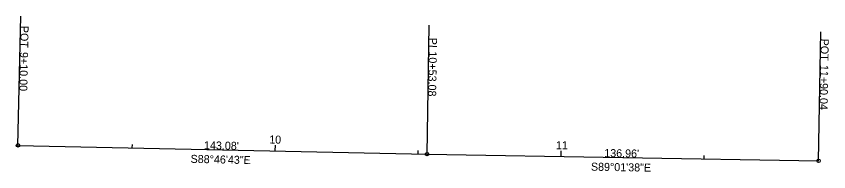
# Model space of a CAD drawing. Extents: x 1652407 to 1652790, y 606471 to 608012.
# Drawn here: x 1652407.2 to 1652691.4, y 606865.9 to 606920.1 of the extents above; entities that cross this region are included whole.
import ezdxf

# ---------------------------------------------------------------- set-up
doc = ezdxf.new("R2010")
doc.units = 0
for name, color, linetype in [('RW_X_CL', 7, 'Continuous'), ('SV_X_Random_Point', 7, 'Continuous'), ('SV_X_Shot_Marker', 7, 'Continuous'), ('UT_X_Water_Cells', 7, 'Continuous'), ('VG_X_Cells', 7, 'Continuous')]:
    doc.layers.add(name, color=color, linetype=linetype)

msp = doc.modelspace()

# ---------------------------------------------------------------- linework, layer by layer
at = {"layer": 'RW_X_CL'}
for p, q in [((1652407.81, 606875.12), (1652550.86, 606872.07)), ((1652550.86, 606872.07), (1652687.8, 606869.74))]:
    msp.add_line(p, q, dxfattribs=at)
at = {"layer": 'SV_X_Random_Point'}
for p, q in [((1652407.81, 606875.12), (1652408.77, 606920.11)), ((1652550.86, 606872.07), (1652551.62, 606917.06)), ((1652687.8, 606869.74), (1652688.56, 606914.74))]:
    msp.add_line(p, q, dxfattribs=at)
for centre in [(1652407.81, 606875.12), (1652550.86, 606872.07), (1652687.8, 606869.74)]:
    msp.add_circle(centre, 0.6, dxfattribs=at)
at = {"layer": 'UT_X_Water_Cells'}
for p, q in [((1652447.8, 606874.27), (1652447.82, 606875.47)), ((1652497.79, 606873.2), (1652497.83, 606875.2)), ((1652547.78, 606872.14), (1652547.8, 606873.34)), ((1652597.77, 606871.27), (1652597.8, 606873.27)), ((1652647.76, 606870.42), (1652647.78, 606871.62))]:
    msp.add_line(p, q, dxfattribs=at)

# ---------------------------------------------------------------- texts
at = {"layer": 'SV_X_Random_Point'}
for s, rotation, p in [('POT', 268.7786, (1652408.74, 606916.81)), ('PI', 269.0273, (1652551.59, 606912.68)), ('POT', 269.0273, (1652688.57, 606912.34)), ('9+10.00', 268.7786, (1652408.55, 606907.69)), ('10+53.08', 269.0273, (1652551.51, 606907.9)), ('11+90.04', 269.0273, (1652688.41, 606903.21))]:
    msp.add_text(s, height=2.8, rotation=rotation, dxfattribs=at).set_placement(p)
at = {"layer": 'SV_X_Shot_Marker'}
for s, rotation, p in [('S88°46\'43"E', 358.7786, (1652468.16, 606869.03)), ('S89°01\'38"E', 359.0273, (1652608.17, 606866.3))]:
    msp.add_text(s, height=2.8, rotation=rotation, dxfattribs=at).set_placement(p)
at = {"layer": 'UT_X_Water_Cells'}
for s, rotation, p in [('10', 358.7786, (1652495.65, 606875.79)), ('11', 359.0273, (1652595.93, 606873.8))]:
    msp.add_text(s, height=2.8, rotation=rotation, dxfattribs=at).set_placement(p)
at = {"layer": 'VG_X_Cells'}
for s, rotation, p in [("143.08'", 358.7786, (1652472.85, 606873.78)), ("136.96'", 359.0273, (1652612.84, 606871.06))]:
    msp.add_text(s, height=2.8, rotation=rotation, dxfattribs=at).set_placement(p)

doc.saveas('drawing.dxf')
